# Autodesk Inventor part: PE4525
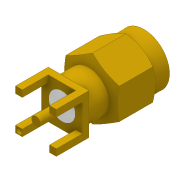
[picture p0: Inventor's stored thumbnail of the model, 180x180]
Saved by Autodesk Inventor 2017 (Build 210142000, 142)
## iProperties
Created: 2020-05
Part Number: PE4525
Material: Aluminum 6061
Document SubType Name: Modeling
Designer: Flash
Density: 2.7 g/cm^3
Appearance: Gold
Author: Flash
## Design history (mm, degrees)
sketch "Sketch1"
  geometry: L1 (3.05, 3.05)-(2.05, 3.05); L2 (2.05, 3.05)-(2.05, 2.05); L3 (2.05, 2.05)-(3.05, 2.05); L4 (3.05, 2.05)-(3.05, 3.05); L5 (3.05, 3.05)-(2.05, 2.05); L6 (2.05, 3.05)-(3.05, 2.05); L7 (3.05, -3.05)-(2.05, -3.05); L8 (2.05, -3.05)-(2.05, -2.05); L9 (2.05, -2.05)-(3.05, -2.05); L10 (3.05, -2.05)-(3.05, -3.05); L11 (3.05, -3.05)-(2.05, -2.05); L12 (2.05, -3.05)-(3.05, -2.05); L13 (-2.05, -2.05)-(-3.05, -2.05); L14 (-3.05, -2.05)-(-3.05, -3.05); L15 (-3.05, -3.05)-(-2.05, -3.05); L16 (-2.05, -3.05)-(-2.05, -2.05); L17 (-2.05, -2.05)-(-3.05, -3.05); L18 (-3.05, -2.05)-(-2.05, -3.05); L19 (-2.05, 3.05)-(-3.05, 3.05); L20 (-3.05, 3.05)-(-3.05, 2.05); L21 (-3.05, 2.05)-(-2.05, 2.05); L22 (-2.05, 2.05)-(-2.05, 3.05); L23 (-2.05, 3.05)-(-3.05, 2.05); L24 (-3.05, 3.05)-(-2.05, 2.05); L25 (0, 0)-(1.01, 0); L26 (1.01, 0)-(0, 0); L27 (0, 0)-(0, -1.047); C1 r 0.65 at (0, 0); 4 further points
  constraints: 54 end point, 9 equal length, 8 midpoint, 5 horizontal, 4 perpendicular, 4 symmetric about line, 1 centre point, 1 coincident, 1 vertical
  dimensions: "d0" = 1 distance of L3.end L2.end; "d1" = 1 distance of L2.end L1.end; "d2" = 1 distance of L8.end L9.end; "d3" = 1 distance of L7.end L8.end; "d4" = 1 distance of L15.end L14.end; "d5" = 1 distance of L14.end L13.end; "d6" = 1 distance of L21.end L20.end; "d7" = 1 distance of L20.end L19.end; "d8" = 5.1 distance of point (2.55, -2.55) point (2.55, 2.55); "d9" = 5.1 distance of point (2.55, -2.55) point (-2.55, -2.55); "d10" = 1.3 diameter of C1
extrude "Extrusion1" new body sketch "Sketch1" distance "d11" = 3.9; taper "d12" = 0 deg
sketch "Sketch2"
  geometry: L1 (-2.05, 3.05)-(-3.05, 3.05) reference; L2 (3.05, -3.05)-(-3.05, -3.05); L3 (-3.05, -3.05)-(-3.05, 3.05); L4 (-3.05, 3.05)-(3.05, 3.05); L5 (3.05, 3.05)-(3.05, -3.05); L6 (3.05, -3.05)-(-3.05, 3.05); L7 (-3.05, -3.05)-(3.05, 3.05); 1 further point
  constraints: 12 end point, 2 midpoint, 2 parallel, 1 horizontal, 1 perpendicular
extrude "Extrusion2" join sketch "Sketch2" distance "d13" = 1; taper "d14" = 0 deg
sketch "Sketch3"
  geometry: C1 r 3.05 at (0, 0); 1 further point
  constraints: 1 centre point, 1 coincident
extrude "Extrusion3" join sketch "Sketch3" distance "d15" = 3; taper "d16" = 0 deg
sketch "Sketch4"
  geometry: L1 (-4, 2.309)-(0, 4.619); L2 (0, 4.619)-(4, 2.309); L3 (4, 2.309)-(4, -2.309); L4 (4, -2.309)-(0, -4.619); L5 (0, -4.619)-(-4, -2.309); L6 (-4, -2.309)-(-4, 2.309); 2 further points
  constraints: 12 end point, 1 coincident, 13 other
  dimensions: "d17" = 8 distance between parallel lines of L3 L6
extrude "Extrusion4" join sketch "Sketch4" distance "d18" = 8.3; taper "d19" = 0 deg
sketch "Sketch5"
  geometry: L1 (0, 0)-(-1.897, 0); L2 (18.472, 3.825)-(14.03, 3.825); L3 (14.03, 3.825)-(14.03, 5.846); L4 (14.03, 5.846)-(18.472, 5.846); L5 (18.472, 5.846)-(18.472, 3.825); L6 (16.2, 4.619)-(16.2, 2.309) reference
  constraints: 10 end point, 2 horizontal, 2 parallel, 1 perpendicular
  dimensions: "d20" = 3.825 distance between parallel lines of L1 L2; "d21" = 2.17 distance between parallel lines of L3 L6
revolve "Revolution1" sketch "Sketch5" stored, may be unused: angle "d22" = 90 deg
sketch "Sketch6"
  geometry: L1 (16.2, 3.825)-(14.03, 3.825) reference; L2 (14.03, 3.825)-(12.993, 5.363); L3 (12.993, 5.363)-(14.03, 5.363); L4 (14.03, 4.619)-(14.03, 2.309) reference; L5 (14.03, 5.363)-(14.03, 3.825); L6 (4.9, 3.05)-(7.9, 3.05) reference; L7 (7.9, 3.05)-(8.748, 5.363); L8 (8.748, 5.363)-(7.9, 5.363); L9 (7.9, 5.363)-(7.9, 3.05); L10 (0, 0)-(-1.133, 0)
  constraints: 14 end point, 3 point on line, 2 perpendicular, 1 collinear, 1 horizontal
revolve "Revolution2" sketch "Sketch6" stored, may be unused: angle "d23" = 90 deg
sketch "Sketch7"
  geometry: C1 r 3.2 at (0, 0); C2 r 0.5 at (0, 0); 1 further point
  constraints: 2 centre point, 2 coincident
  dimensions: "d24" = 6.4 diameter of C1; "d25" = 1 diameter of C2
extrude "Extrusion5" cut sketch "Sketch7" distance "d26" = 3; taper "d27" = 0 deg
sketch "Sketch8"
  geometry: L1 (-3.05, -3.05)-(-2.05, -3.05) reference; L2 (-2.05, -3.05)-(-2.05, -2.05) reference; L3 (-2.05, -2.05)-(-3.05, -2.05) reference; L4 (-3.05, -2.05)-(-3.05, -3.05) reference; C1 r 0.451 at (-2.55, -2.55); 1 further point
  constraints: 1 centre point
extrude "Extrusion6" cut sketch "Sketch8" distance "d28" = 0.5; taper "d29" = 0 deg
sketch "Sketch9"
  geometry: C1 r 3.2 at (0, 0) reference; C2 r 0.65 at (0, 0) reference; C3 r 2.7 at (0, 0); 1 further point
  constraints: 1 centre point, 1 coincident
  dimensions: "d30" = 5.4 diameter of C3
extrude "Extrusion7" cut sketch "Sketch9" distance "d31" = 1.8; taper "d32" = 0 deg
fillet "Fillet1" dims "d33" = 0.4
fillet "Fillet2" dims "d34" = 0.4
sketch "Sketch10"
  geometry: C1 r 0.5 at (0, 0) reference; C2 r 2 at (0, 0); 1 further point
  constraints: 1 centre point, 1 coincident
  dimensions: "d35" = 4 diameter of C2
extrude "Extrusion8" cut sketch "Sketch10" distance "d36" = 0.01; taper "d37" = 0 deg
body "Solid1"
node "Projected Loop1"
